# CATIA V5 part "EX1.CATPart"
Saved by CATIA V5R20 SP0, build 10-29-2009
Part number: Pièce1
Bounding box of the stored display mesh (mm): x -40 to 70, y -7.544 to 66.095, z -1 to 1
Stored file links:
  E:\Nouveau dossier\tarek\mécaniquee\FAO\CATIA\CATIA CATIA\EX1.CATPart
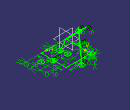
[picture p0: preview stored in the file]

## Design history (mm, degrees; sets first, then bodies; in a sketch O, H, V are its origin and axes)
Body1 (main body)
  Sketch1 on xy-plane, origin (0, 0, 0), H (1, 0, 0), V (0, 1, 0)
    point P1 (50, 50)
    line L1 (50, 50) -> (0, 50)
    line L2 (0, 50) -> (0, 0)
    line L3 (0, 0) -> (50, 0)
    line L4 (50, 0) -> (50, 50)
    point P2 (0, 50)
    circle A1 centre (25, 28) radius 5
    point P4 (25, 28)
    line L5 (0, 0) -> (26.4884, 14.0841)
    circle A2 centre (26.4884, 14.0841) radius 5
    circle A3 centre (50, 25) radius 5
    point P6 (50, 25)
    circle A4 centre (0, 50) radius 5
    point P7 (0, 25)
    point P8 (-0.03, 28)
    line L6 (-0.03, 28) -> (19.97, 50)
    point P9 (19.97, 50)
    line L7 (19.97, 50) -> (30.0601, 61.0991)
    point P10 (30.0601, 61.0991)
    circle A5 centre (30.0601, 61.0991) radius 5
    line L8 (0, 0) -> (-40, 0)
    line L9 (-0.03, 28) -> (-32.3426, -7.5439)
    circle A6 centre (-25.4845, 0) radius 5
    point P13 (-25.4845, 0)
    circle A7 centre (65, 15) radius 5
    point P14 (65, 15)
    distance P1 V = 50
    distance P1 H = 50
    radius A1 = 5
    distance P4 L3 = 28
    distance P4 L2 = 25
    length L5 = 30
    angle L5 H = 28
    radius A2 = 5
    radius A3 = 5
    radius A4 = 5
    distance P9 P2 = 19.97
    length L7 = 15
    radius A5 = 5
    distance P8 P9 = 29.7321
    radius A6 = 5
    distance P8 L3 = 28
    angle L9 L6 = 180
    radius A7 = 5
    distance P14 L3 = 15
    distance P14 L4 = 15
    horizontal: L1 H, L3 H, L8 H
    vertical: L2 V, L4 V
    midpoint: P6 L4, P7 L2
    coincidence: P9 L1, P10 L6, P13 L9, P13 L8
